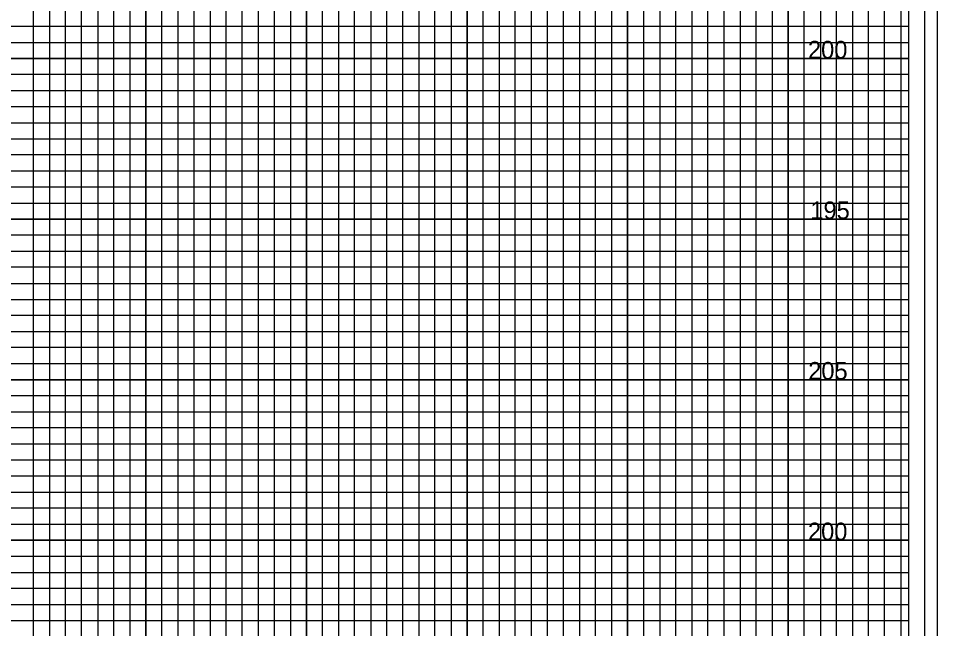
# Model space of a CAD drawing. Extents: x -4 to 103, y -2 to 209.
# Drawn here: x 74.78 to 103.4, y 32.25 to 51.25 of the extents above; entities that cross this region are included whole.
import ezdxf

# ---------------------------------------------------------------- set-up
doc = ezdxf.new("R2010")
doc.units = 0
for name, color, linetype in [('Exist XS Ground Line', 7, 'Continuous'), ('Old_Level_10', 7, 'Continuous'), ('Old_Level_5', 7, 'Continuous'), ('Old_Level_8', 7, 'Continuous'), ('Prop XS Finish Grade Earthwork', 7, 'Continuous'), ('Prop XS Finish Grade Pavement', 7, 'Continuous'), ('Prop XS SE Text', 7, 'Continuous')]:
    doc.layers.add(name, color=color, linetype=linetype)

msp = doc.modelspace()

# ---------------------------------------------------------------- linework, layer by layer
at = {"layer": 'Exist XS Ground Line'}
msp.add_lwpolyline([(103, 66), (-2.8, 66), (-2.8, -1), (103, -1)], close=True, dxfattribs=at)
at = {"layer": 'Old_Level_10'}
for p, q in [((91.25, 0), (91.25, 63.425)), ((93.75, 0), (93.75, 63.425)), ((96.25, 0), (96.25, 63.425)), ((98.75, 0), (98.75, 63.425)), ((101.25, 0), (101.25, 63.425)), ((76.25, 0), (76.25, 62)), ((78.75, 0), (78.75, 62)), ((81.25, 0), (81.25, 62)), ((83.75, 0), (83.75, 62)), ((86.25, 0), (86.25, 62)), ((88.75, 0), (88.75, 62)), ((0, 50), (102.5, 50)), ((0, 47.5), (102.5, 47.5)), ((0, 45), (102.5, 45)), ((0, 42.5), (102.5, 42.5)), ((0, 40), (102.5, 40)), ((0, 37.5), (102.5, 37.5)), ((0, 35), (102.5, 35)), ((0, 32.5), (102.5, 32.5))]:
    msp.add_line(p, q, dxfattribs=at)
at = {"layer": 'Old_Level_5'}
msp.add_lwpolyline([(103.4, 67.4), (-3.5, 67.4), (-3.5, -2.425), (103.4, -2.425)], close=True, dxfattribs=at)
at = {"layer": 'Old_Level_8'}
for points in [[(91.25, 0), (91.25, 63.425), (93.75, 63.425), (93.75, 0)], [(96.25, 0), (96.25, 63.425), (98.75, 63.425), (98.75, 0)], [(101.25, 0), (101.25, 63.425)], [(76.25, 0), (76.25, 62), (78.75, 62), (78.75, 0)], [(81.25, 0), (81.25, 62), (83.75, 62), (83.75, 0)], [(86.25, 0), (86.25, 62), (88.75, 62), (88.75, 0)], [(0, 47.5), (102.5, 47.5), (102.5, 50), (0, 50)], [(0, 42.5), (102.5, 42.5), (102.5, 45), (0, 45)], [(0, 37.5), (102.5, 37.5), (102.5, 40), (0, 40)], [(0, 32.5), (102.5, 32.5), (102.5, 35), (0, 35)]]:
    msp.add_lwpolyline(points, dxfattribs=at)
at = {"layer": 'Prop XS Finish Grade Earthwork'}
for points in [[(90.25, 0), (90.25, 63.425), (90.75, 63.425), (90.75, 0)], [(91.75, 0), (91.75, 63.425), (92.25, 63.425), (92.25, 0)], [(92.75, 0), (92.75, 63.425), (93.25, 63.425), (93.25, 0)], [(94.25, 0), (94.25, 63.425), (94.75, 63.425), (94.75, 0)], [(95.25, 0), (95.25, 63.425), (95.75, 63.425), (95.75, 0)], [(96.75, 0), (96.75, 63.425), (97.25, 63.425), (97.25, 0)], [(97.75, 0), (97.75, 63.425), (98.25, 63.425), (98.25, 0)], [(99.25, 0), (99.25, 63.425), (99.75, 63.425), (99.75, 0)], [(100.25, 0), (100.25, 63.425)], [(100.25, 63.425), (100.75, 63.425), (100.75, 0), (101.75, 0), (101.75, 63.425), (102.25, 63.425), (102.25, 0)], [(75.25, 0), (75.25, 62), (75.75, 62), (75.75, 0)], [(76.75, 0), (76.75, 62), (77.25, 62), (77.25, 0)], [(77.75, 0), (77.75, 62), (78.25, 62), (78.25, 0)], [(79.25, 0), (79.25, 62), (79.75, 62), (79.75, 0)], [(80.25, 0), (80.25, 62), (80.75, 62), (80.75, 0)], [(81.75, 0), (81.75, 62), (82.25, 62), (82.25, 0)], [(82.75, 0), (82.75, 62), (83.25, 62), (83.25, 0)], [(84.25, 0), (84.25, 62), (84.75, 62), (84.75, 0)], [(85.25, 0), (85.25, 62), (85.75, 62), (85.75, 0)], [(86.75, 0), (86.75, 62), (87.25, 62), (87.25, 0)], [(87.75, 0), (87.75, 62), (88.25, 62), (88.25, 0)], [(89.25, 0), (89.25, 62), (89.75, 62), (89.75, 0)], [(0, 50.5), (102.5, 50.5), (102.5, 51), (0, 51)], [(0, 49), (102.5, 49), (102.5, 49.5), (0, 49.5)], [(0, 48), (102.5, 48), (102.5, 48.5), (0, 48.5)], [(0, 46.5), (102.5, 46.5), (102.5, 47), (0, 47)], [(0, 45.5), (102.5, 45.5), (102.5, 46), (0, 46)], [(0, 44), (102.5, 44), (102.5, 44.5), (0, 44.5)], [(0, 43), (102.5, 43), (102.5, 43.5), (0, 43.5)], [(0, 41.5), (102.5, 41.5), (102.5, 42), (0, 42)], [(0, 40.5), (102.5, 40.5), (102.5, 41), (0, 41)], [(0, 39), (102.5, 39), (102.5, 39.5), (0, 39.5)], [(0, 38), (102.5, 38), (102.5, 38.5), (0, 38.5)], [(0, 36.5), (102.5, 36.5), (102.5, 37), (0, 37)], [(0, 35.5), (102.5, 35.5), (102.5, 36), (0, 36)], [(0, 34), (102.5, 34), (102.5, 34.5), (0, 34.5)], [(0, 33), (102.5, 33), (102.5, 33.5), (0, 33.5)]]:
    msp.add_lwpolyline(points, dxfattribs=at)
at = {"layer": 'Prop XS SE Text'}
msp.add_lwpolyline([(102.5, 65), (0, 65), (0, 0), (102.5, 0)], close=True, dxfattribs=at)

# ---------------------------------------------------------------- texts
at = {"layer": 'Prop XS Finish Grade Pavement'}
for s, p in [('200', (99.364, 50)), ('195', (99.438, 45)), ('205', (99.372, 40)), ('200', (99.364, 35))]:
    msp.add_text(s, height=0.55, dxfattribs=at).set_placement(p)

doc.saveas('drawing.dxf')
